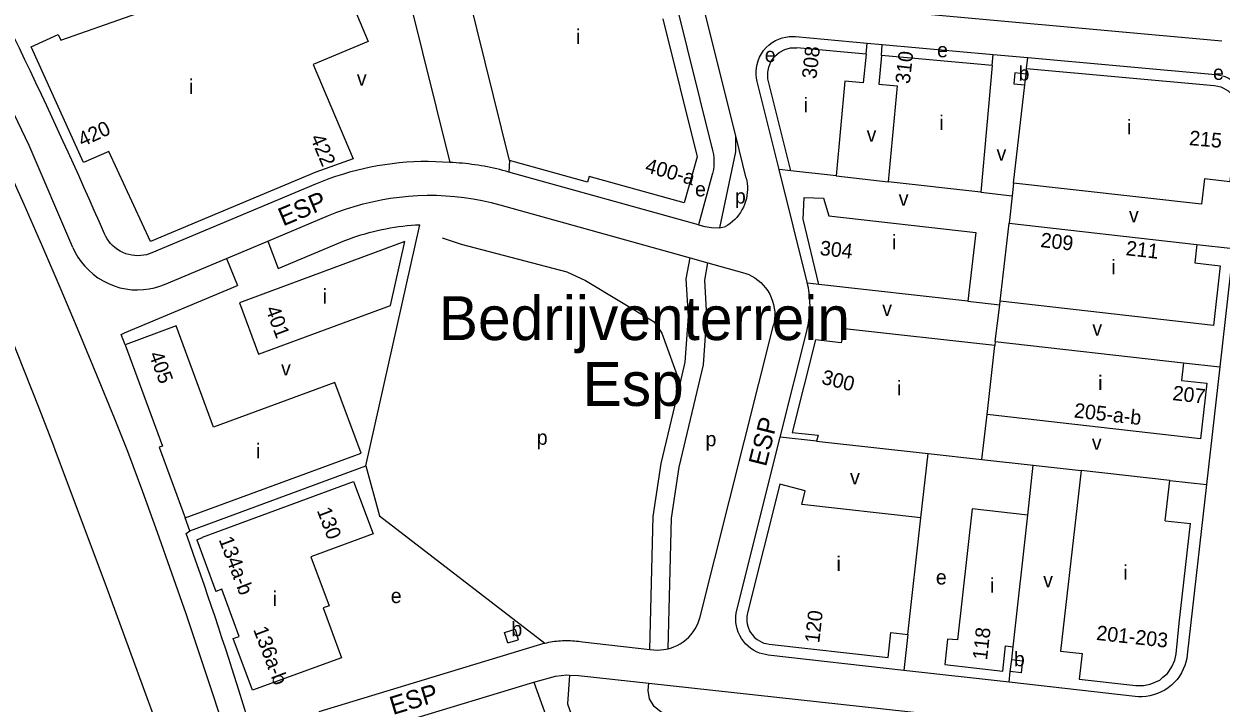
# Model space of a CAD drawing. Extents: x 161394 to 163917, y 388470 to 389774.
# Drawn here: x 162013.8 to 162341, y 388680.9 to 388866.6 of the extents above; entities that cross this region are included whole.
import ezdxf

# ---------------------------------------------------------------- set-up
doc = ezdxf.new("R2010")
doc.units = 0
for name, color, linetype in [('BLT_Basislijn', 7, 'Continuous'), ('BLT_Bebouwing', 7, 'Continuous'), ('BLT_Centroide', 7, 'Continuous'), ('BLT_Huisnummer', 7, 'Continuous'), ('BLT_Huisnummer_reeks', 7, 'Continuous'), ('BLT_Onderverdeling_panden', 7, 'Continuous'), ('BLT_Sport_parknaam', 7, 'Continuous'), ('BLT_Straatnaam', 7, 'Continuous')]:
    doc.layers.add(name, color=color, linetype=linetype)

msp = doc.modelspace()

# ---------------------------------------------------------------- linework, layer by layer
at = {"layer": 'BLT_Basislijn'}
for p, q in [((162208.3, 388835.99), (162177.66, 388959.39)), ((162184.9, 388900.77), (162201.98, 388831.99)), ((162115.96, 388886.06), (162130.14, 388828.74)), ((162224.68, 388863.18), (162244.2, 388861.4)), ((162243.91, 388858.4), (162244.2, 388861.4)), ((162244.2, 388861.4), (162248.37, 388861.03)), ((162248.1, 388858), (162248.37, 388861.03)), ((162248.37, 388861.03), (162278.68, 388858.28)), ((162278.4, 388855.26), (162278.68, 388858.28)), ((162278.68, 388858.28), (162288.15, 388857.42)), ((162287.81, 388854.44), (162288.15, 388857.42)), ((162288.15, 388857.42), (162339.39, 388852.77)), ((162220.16, 388826.82), (162214.18, 388850.93)), ((162211.16, 388824.48), (162208.3, 388835.99)), ((162146.51, 388829.3), (162146.3, 388826.13)), ((162198.08, 388811.72), (162146.3, 388826.13)), ((162201.89, 388825.42), (162198.08, 388811.72)), ((162223.34, 388826.46), (162220.16, 388826.82)), ((162227.81, 388796.04), (162220.16, 388826.82)), ((162093.4, 388822.78), (162048.7, 388804)), ((162235.71, 388825.07), (162249.94, 388823.46)), ((162284.26, 388823.09), (162283.87, 388819.63)), ((162275.28, 388820.6), (162283.87, 388819.63)), ((162283.87, 388819.63), (162283.02, 388812.13)), ((162107.21, 388745.76), (162121.96, 388811.73)), ((162203.94, 388810.88), (162205.52, 388811.2)), ((162080.43, 388807.25), (162083.22, 388799.74)), ((162083.22, 388799.74), (162100.38, 388806.95)), ((162334.33, 388806.33), (162344.29, 388805.2)), ((162069.14, 388802.5), (162072.16, 388795.09)), ((162344.29, 388805.2), (162340.62, 388772.81)), ((162231.06, 388795.4), (162227.88, 388795.76)), ((162041.25, 388782.11), (162072.16, 388795.09)), ((162271.76, 388790.8), (162280.49, 388789.81)), ((162279.22, 388779.76), (162280.49, 388789.81)), ((162280.49, 388789.81), (162280.61, 388790.77)), ((162220.48, 388753.65), (162227.8, 388782.93)), ((162330.69, 388773.97), (162340.62, 388772.81)), ((162340.62, 388772.81), (162336.99, 388740.67)), ((162208.62, 388706.26), (162220.48, 388753.65)), ((162230.39, 388752.55), (162220.48, 388753.65)), ((162258.9, 388731.55), (162260.87, 388749.17)), ((162275.6, 388747.53), (162289.56, 388745.96)), ((162059.13, 388728.01), (162107.21, 388745.76)), ((162288.1, 388732.32), (162289.56, 388745.96)), ((162289.56, 388745.96), (162302.68, 388744.48)), ((162326.94, 388741.74), (162336.99, 388740.67)), ((162336.99, 388740.67), (162331.72, 388694.05)), ((162255.34, 388699.68), (162254.28, 388689.82)), ((162254.28, 388689.82), (162217.19, 388694.02)), ((162283, 388686.57), (162254.28, 388689.82)), ((162317.45, 388682.68), (162283, 388686.57))]:
    msp.add_line(p, q, dxfattribs=at)
for points in [[(162027.15, 388805.45), (162015.14, 388833.36), (161997.8, 388869.55), (161974.18, 388914.29), (161961.92, 388936.27)], [(162035.78, 388809.19), (162034.39, 388812.39), (162032.98, 388815.59), (162031.57, 388818.79), (162030.16, 388821.98), (162028.73, 388825.16), (162027.3, 388828.35), (162025.85, 388831.53), (162024.4, 388834.7), (162022.94, 388837.88), (162021.48, 388841.05), (162020, 388844.21), (162018.52, 388847.37), (162017.03, 388850.53), (162015.53, 388853.68), (162014.02, 388856.83), (162012.51, 388859.98), (162010.98, 388863.12), (162009.45, 388866.26), (162007.91, 388869.39)], [(162341.2, 388861.95), (162241.66, 388870.97)], [(162214.18, 388850.93), (162214.01, 388851.78), (162213.91, 388852.68), (162213.89, 388853.62), (162213.97, 388854.59), (162214.15, 388855.57), (162214.43, 388856.56), (162214.82, 388857.53), (162215.33, 388858.46), (162215.93, 388859.34), (162216.63, 388860.16), (162217.41, 388860.89), (162218.26, 388861.53), (162219.16, 388862.07), (162220.09, 388862.5), (162221.03, 388862.83), (162221.98, 388863.05), (162222.91, 388863.18), (162223.81, 388863.22), (162224.68, 388863.18)], [(162339.39, 388852.77), (162340.14, 388852.68), (162340.9, 388852.53), (162341.67, 388852.31), (162342.44, 388852.03), (162343.19, 388851.67), (162343.92, 388851.24), (162344.63, 388850.75), (162345.29, 388850.19), (162345.91, 388849.57), (162346.47, 388848.9), (162346.96, 388848.18), (162347.39, 388847.43), (162347.75, 388846.65), (162348.04, 388845.85), (162348.25, 388845.04), (162348.4, 388844.24), (162348.47, 388843.44), (162348.49, 388842.67), (162348.44, 388841.91)], [(162087.86, 388607.87), (162087.24, 388610.3), (162084.83, 388619.37), (162082.34, 388628.43), (162079.77, 388637.46), (162079.66, 388637.83), (162076.25, 388649.13), (162072.76, 388660.41), (162069.19, 388671.66), (162065.55, 388682.89), (162061.84, 388694.09), (162058.05, 388705.27), (162054.18, 388716.42), (162050.23, 388727.55), (162046.22, 388738.65), (162042.12, 388749.72), (162038.47, 388758.81), (162033.68, 388770.55), (162028.82, 388782.27), (162023.88, 388793.95), (162018.87, 388805.6), (162013.78, 388817.22), (162008.62, 388828.81), (162003.19, 388840.81)], [(162203.94, 388810.88), (162208.3, 388831.66), (162208.3, 388835.99)], [(162201.98, 388831.99), (162202.06, 388831.65), (162202.13, 388831.31), (162202.19, 388830.97), (162202.24, 388830.62), (162202.29, 388830.28), (162202.32, 388829.93), (162202.34, 388829.58), (162202.36, 388829.23), (162202.36, 388828.88), (162202.36, 388828.52), (162202.34, 388828.17), (162202.32, 388827.82), (162202.29, 388827.47), (162202.24, 388827.13), (162202.19, 388826.78), (162202.13, 388826.44), (162202.06, 388826.1), (162201.98, 388825.76), (162201.89, 388825.42)], [(162130.14, 388828.74), (162128.19, 388828.87), (162126.22, 388828.96), (162124.25, 388828.99), (162122.27, 388828.98), (162120.3, 388828.91), (162118.32, 388828.79), (162116.34, 388828.63), (162114.36, 388828.41), (162112.39, 388828.14), (162110.43, 388827.82), (162108.48, 388827.45), (162106.54, 388827.04), (162104.61, 388826.57), (162102.69, 388826.05), (162100.79, 388825.49), (162098.91, 388824.88), (162097.06, 388824.23), (162095.22, 388823.53), (162093.4, 388822.78)], [(162146.3, 388826.13), (162145.47, 388826.36), (162144.64, 388826.59), (162143.8, 388826.8), (162142.96, 388827), (162142.12, 388827.19), (162141.27, 388827.37), (162140.43, 388827.54), (162139.58, 388827.7), (162138.73, 388827.85), (162137.87, 388827.99), (162137.02, 388828.12), (162136.16, 388828.23), (162135.3, 388828.34), (162134.45, 388828.43), (162133.59, 388828.52), (162132.73, 388828.59), (162131.87, 388828.65), (162131.01, 388828.7), (162130.14, 388828.74)], [(162211.16, 388824.48), (162211.32, 388823.73), (162211.44, 388822.96), (162211.5, 388822.17), (162211.51, 388821.36), (162211.47, 388820.54), (162211.37, 388819.72), (162211.21, 388818.9), (162210.99, 388818.09), (162210.72, 388817.29), (162210.39, 388816.52), (162210.01, 388815.77), (162209.57, 388815.05), (162209.1, 388814.36), (162208.57, 388813.72), (162208.02, 388813.12), (162207.43, 388812.57), (162206.81, 388812.06), (162206.18, 388811.61), (162205.52, 388811.2)], [(162097.01, 388814.21), (162099.3, 388815.13), (162101.65, 388815.97), (162104.02, 388816.74), (162106.44, 388817.42), (162108.89, 388818.02), (162111.36, 388818.53), (162113.85, 388818.96), (162116.37, 388819.3), (162118.89, 388819.55), (162121.43, 388819.71), (162123.96, 388819.78), (162126.5, 388819.76), (162129.02, 388819.65), (162131.54, 388819.45), (162134.05, 388819.16), (162136.53, 388818.79), (162138.98, 388818.33), (162141.41, 388817.79), (162143.81, 388817.17)], [(162143.81, 388817.17), (162195.87, 388802.68)], [(162080.43, 388807.25), (162097.01, 388814.21)], [(162048.7, 388804), (162048, 388803.74), (162047.27, 388803.52), (162046.5, 388803.36), (162045.7, 388803.26), (162044.89, 388803.23), (162044.05, 388803.26), (162043.22, 388803.36), (162042.39, 388803.54), (162041.57, 388803.79), (162040.78, 388804.11), (162040.01, 388804.49), (162039.29, 388804.94), (162038.62, 388805.45), (162037.99, 388806), (162037.43, 388806.59), (162036.92, 388807.21), (162036.48, 388807.86), (162036.1, 388808.52), (162035.78, 388809.19)], [(162100.38, 388806.95), (162101.46, 388807.39), (162102.55, 388807.8), (162103.65, 388808.2), (162104.75, 388808.58), (162105.87, 388808.93), (162106.99, 388809.27), (162108.12, 388809.59), (162109.25, 388809.88), (162110.39, 388810.16), (162111.54, 388810.41), (162112.68, 388810.64), (162113.84, 388810.85), (162114.99, 388811.04), (162116.15, 388811.21), (162117.31, 388811.36), (162118.47, 388811.48), (162119.64, 388811.58), (162120.8, 388811.67), (162121.96, 388811.73)], [(162198.08, 388811.72), (162199.85, 388811.26), (162201.68, 388810.97), (162203.94, 388810.88)], [(162069.14, 388802.5), (162080.43, 388807.25)], [(162128.03, 388808.11), (162133.24, 388806.41), (162162.1, 388798.84), (162167.23, 388796.44), (162186.04, 388785.13), (162188.14, 388782.09), (162193.08, 388768.2)], [(162027.15, 388805.45), (162027.77, 388804.15), (162028.51, 388802.87), (162029.37, 388801.61), (162030.35, 388800.4), (162031.45, 388799.26), (162032.66, 388798.19), (162033.97, 388797.21), (162035.37, 388796.35), (162036.85, 388795.6), (162038.39, 388794.98), (162039.97, 388794.5), (162041.58, 388794.15), (162043.2, 388793.95), (162044.81, 388793.89), (162046.4, 388793.96), (162047.94, 388794.15), (162049.43, 388794.46), (162050.85, 388794.88), (162052.2, 388795.39)], [(162052.2, 388795.39), (162069.14, 388802.5)], [(162193.08, 388768.2), (162194.49, 388774.16), (162195.41, 388786.62), (162194.78, 388796.92), (162195.87, 388802.68)], [(162195.87, 388802.68), (162200.71, 388801.33)], [(162189.79, 388695.72), (162190.74, 388731.5), (162192.85, 388745.42), (162199.45, 388773.4), (162200.42, 388786.59), (162199.81, 388796.6), (162200.71, 388801.33)], [(162200.71, 388801.33), (162210.19, 388798.69)], [(162210.19, 388798.69), (162211.04, 388798.42), (162211.89, 388798.07), (162212.74, 388797.65), (162213.56, 388797.16), (162214.36, 388796.59), (162215.12, 388795.94), (162215.83, 388795.22), (162216.48, 388794.44), (162217.07, 388793.6), (162217.59, 388792.72), (162218.03, 388791.79), (162218.38, 388790.84), (162218.65, 388789.86), (162218.84, 388788.88), (162218.95, 388787.91), (162218.97, 388786.95), (162218.92, 388786), (162218.8, 388785.09), (162218.61, 388784.22)], [(162227.8, 388782.93), (162227.95, 388783.59), (162228.09, 388784.25), (162228.22, 388784.92), (162228.32, 388785.59), (162228.41, 388786.27), (162228.49, 388786.95), (162228.54, 388787.63), (162228.58, 388788.31), (162228.6, 388789), (162228.61, 388789.68), (162228.59, 388790.37), (162228.56, 388791.05), (162228.52, 388791.73), (162228.45, 388792.41), (162228.37, 388793.09), (162228.27, 388793.76), (162228.15, 388794.43), (162228.02, 388795.1), (162227.88, 388795.76)], [(162227.88, 388795.76), (162227.87, 388795.77), (162227.87, 388795.79), (162227.87, 388795.8), (162227.86, 388795.82), (162227.86, 388795.83), (162227.85, 388795.85), (162227.85, 388795.86), (162227.85, 388795.88), (162227.84, 388795.89), (162227.84, 388795.91), (162227.84, 388795.92), (162227.83, 388795.93), (162227.83, 388795.95), (162227.83, 388795.96), (162227.82, 388795.98), (162227.82, 388795.99), (162227.82, 388796.01), (162227.81, 388796.02), (162227.81, 388796.04)], [(162198.57, 388704.48), (162218.61, 388784.22)], [(162099.69, 388494.38), (162091.65, 388531.25), (162090.66, 388536.53), (162089.19, 388544.02), (162087.64, 388551.5), (162086, 388558.97), (162084.3, 388566.41), (162082.51, 388573.84), (162080.64, 388581.25), (162078.7, 388588.64), (162076.68, 388596.01), (162074.59, 388603.36), (162072.41, 388610.68), (162070.16, 388617.98), (162067.84, 388625.26), (162065.43, 388632.51), (162062.96, 388639.74), (162060.4, 388646.94), (162036.19, 388712.95), (162022.35, 388749.92), (162021.79, 388751.4), (162017.9, 388761.55), (162013.94, 388771.67), (162009.9, 388781.76)], [(162041.38, 388778.89), (162040.34, 388781.73), (162041.25, 388782.11)], [(162184.79, 388695.57), (162185.75, 388731.95), (162187.94, 388746.37), (162193.08, 388768.2)], [(162107.21, 388745.76), (162110.92, 388732.1), (162156.12, 388697.27)], [(162059.13, 388728.01), (162057.83, 388731.53)], [(162076.06, 388672.96), (162072.49, 388684.45), (162070.66, 388690.18), (162069.74, 388693.05), (162068.81, 388695.91), (162067.87, 388698.77), (162066.93, 388701.62), (162065.98, 388704.48), (162065.02, 388707.33), (162064.05, 388710.18), (162063.08, 388713.03), (162062.1, 388715.87), (162061.12, 388718.72), (162060.13, 388721.56), (162059.13, 388724.4), (162058.12, 388727.23), (162059.13, 388728.01)], [(162189.79, 388695.72), (162190.73, 388696.01), (162191.41, 388696.26), (162192.3, 388696.65), (162193.15, 388697.13), (162193.97, 388697.67), (162194.74, 388698.27), (162195.45, 388698.93), (162196.1, 388699.65), (162196.69, 388700.4), (162197.21, 388701.18), (162197.65, 388701.99), (162198.03, 388702.82), (162198.34, 388703.65), (162198.57, 388704.48)], [(162217.19, 388694.02), (162216.4, 388694.13), (162215.59, 388694.32), (162214.78, 388694.58), (162213.97, 388694.92), (162213.18, 388695.35), (162212.41, 388695.85), (162211.69, 388696.43), (162211.01, 388697.08), (162210.4, 388697.8), (162209.85, 388698.58), (162209.39, 388699.41), (162209, 388700.27), (162208.71, 388701.15), (162208.5, 388702.04), (162208.37, 388702.93), (162208.33, 388703.8), (162208.36, 388704.66), (162208.46, 388705.48), (162208.62, 388706.26)], [(162156.12, 388697.27), (162156.65, 388697.4), (162157.18, 388697.51), (162157.71, 388697.61), (162158.25, 388697.7), (162158.79, 388697.78), (162159.33, 388697.84), (162159.88, 388697.9), (162160.42, 388697.94), (162160.97, 388697.97), (162161.52, 388697.99), (162162.06, 388698), (162162.61, 388698), (162163.16, 388697.98), (162163.7, 388697.95), (162164.25, 388697.91), (162164.79, 388697.86), (162165.33, 388697.8), (162165.87, 388697.73), (162166.41, 388697.64)], [(162166.41, 388697.64), (162184.79, 388695.57)], [(162156.12, 388697.27), (162094.32, 388678.5)], [(162184.79, 388695.57), (162185.95, 388695.43), (162186.83, 388695.39), (162187.73, 388695.42), (162188.65, 388695.51), (162189.79, 388695.72)], [(162283.73, 388692.77), (162284.11, 388696.28)], [(162331.72, 388694.05), (162331.57, 388693.09), (162331.35, 388692.11), (162331.04, 388691.13), (162330.64, 388690.15), (162330.15, 388689.2), (162329.58, 388688.27), (162328.92, 388687.38), (162328.18, 388686.54), (162327.37, 388685.77), (162326.49, 388685.07), (162325.56, 388684.45), (162324.58, 388683.92), (162323.56, 388683.47), (162322.53, 388683.12), (162321.49, 388682.86), (162320.45, 388682.69), (162319.42, 388682.61), (162318.42, 388682.61), (162317.45, 388682.68)], [(162153.13, 388686.65), (162159.08, 388688.24), (162162.14, 388688.58), (162162.85, 388688.54)], [(162162.85, 388688.54), (162162.3, 388680.7), (162171.01, 388656.24), (162175.86, 388657.98)], [(162162.85, 388688.54), (162165.36, 388688.4), (162184.54, 388686.31)], [(162283, 388686.57), (162283.34, 388689.5)], [(162118.23, 388676.05), (162153.13, 388686.65)], [(162153.13, 388686.65), (162156.39, 388677.5)], [(162190.14, 388677.75), (162187.93, 388678.41), (162185.98, 388679.93), (162184.73, 388682.07), (162184.37, 388684.35), (162184.54, 388686.31)], [(162184.54, 388686.31), (162313.68, 388672.24)]]:
    msp.add_lwpolyline(points, dxfattribs=at)
at = {"layer": 'BLT_Bebouwing'}
for p, q in [((162146.51, 388829.3), (162132.02, 388887.65)), ((162188.42, 388867.99), (162197.76, 388830.33)), ((162243.91, 388858.4), (162225.01, 388860.1)), ((162167.8, 388823.37), (162146.51, 388829.3)), ((162197.76, 388830.33), (162194.24, 388817.67)), ((162168.23, 388824.91), (162167.8, 388823.37)), ((162194.24, 388817.67), (162168.23, 388824.91)), ((162238.05, 388783.23), (162237.09, 388779.45)), ((162279.09, 388778.66), (162238.05, 388783.23)), ((162230.06, 388780.24), (162223.72, 388754.89)), ((162237.09, 388779.45), (162230.06, 388780.24)), ((162279.22, 388779.76), (162279.09, 388778.66)), ((162279.22, 388779.76), (162330.69, 388773.97)), ((162330.69, 388773.97), (162330.12, 388769.13)), ((162330.12, 388769.13), (162337.09, 388768.35)), ((162337.09, 388768.35), (162335.37, 388753.18)), ((162275.6, 388747.53), (162276.98, 388759.79)), ((162335.37, 388753.18), (162276.98, 388759.79)), ((162230.79, 388754.12), (162230.39, 388752.55)), ((162230.39, 388752.55), (162260.87, 388749.17)), ((162260.87, 388749.17), (162275.6, 388747.53)), ((162302.68, 388744.48), (162297.05, 388695.11)), ((162326.94, 388741.74), (162302.68, 388744.48)), ((162220.31, 388740.72), (162211.53, 388705.53)), ((162227.25, 388738.96), (162220.31, 388740.72)), ((162325.67, 388730.76), (162326.94, 388741.74)), ((162226.35, 388735.22), (162227.25, 388738.96)), ((162258.9, 388731.55), (162226.35, 388735.22)), ((162255.34, 388699.68), (162258.9, 388731.55)), ((162284.11, 388696.28), (162288.1, 388732.32)), ((162325.67, 388730.76), (162332.56, 388729.97)), ((162060.98, 388725.58), (162066.21, 388711.42)), ((162145.11, 388700.2), (162147.98, 388701.07)), ((162147.98, 388701.07), (162148.86, 388698.2)), ((162145.99, 388697.33), (162145.11, 388700.2)), ((162145.99, 388697.33), (162148.86, 388698.2)), ((162249.92, 388693.32), (162250.68, 388700.18)), ((162250.68, 388700.18), (162255.34, 388699.68)), ((162217.45, 388697.01), (162249.92, 388693.32)), ((162297.05, 388695.11), (162302.96, 388694.44)), ((162302.96, 388694.44), (162302.15, 388687.47)), ((162265.45, 388691.4), (162281.31, 388689.64)), ((162283.34, 388689.5), (162283.73, 388692.77)), ((162302.15, 388687.47), (162317.66, 388685.68))]:
    msp.add_line(p, q, dxfattribs=at)
for points in [[(162015.75, 388860.39), (162023.09, 388863.77), (162023.86, 388862.24), (162081.55, 388882.48), (162096.9, 388887.92), (162107.86, 388861.83), (162092.8, 388855.5), (162103.73, 388829.7), (162093.51, 388826.06), (162069.87, 388816.15), (162048.35, 388807.09), (162048.34, 388807.1), (162048.35, 388807.09), (162036.94, 388831.79), (162030.04, 388828.74)], [(162072.67, 388790.4), (162077.87, 388776.3), (162113.98, 388789.65), (162117.87, 388807.13)]]:
    msp.add_lwpolyline(points, close=True, dxfattribs=at)
for points in [[(162223.34, 388826.46), (162217.09, 388851.65), (162217.06, 388853.47), (162217.31, 388854.85), (162217.91, 388856.31), (162218.92, 388857.72), (162220.17, 388858.81), (162221.68, 388859.63), (162223.31, 388860.07), (162225.01, 388860.1)], [(162243.91, 388858.4), (162243.16, 388850.52), (162238.15, 388850.99), (162235.71, 388825.07)], [(162248.1, 388858), (162247.39, 388850.14), (162252.4, 388849.66), (162249.94, 388823.46)], [(162278.4, 388855.26), (162248.1, 388858)], [(162278.4, 388855.26), (162275.28, 388820.6)], [(162287.64, 388852.94), (162284.62, 388853.24), (162284.33, 388850.26), (162287.3, 388849.97)], [(162287.64, 388852.94), (162287.81, 388854.44)], [(162287.81, 388854.44), (162339.11, 388849.78), (162340.07, 388849.63), (162340.9, 388849.4), (162341.64, 388849.08), (162342.29, 388848.73), (162342.9, 388848.3), (162343.45, 388847.82), (162343.94, 388847.26), (162344.43, 388846.63), (162344.79, 388845.97), (162345.05, 388845.4), (162345.24, 388844.73), (162345.43, 388843.96), (162345.5, 388843.35), (162345.5, 388842.68), (162345.44, 388841.77), (162343.36, 388823.49)], [(162284.26, 388823.09), (162287.3, 388849.97)], [(162235.71, 388825.07), (162223.34, 388826.46)], [(162275.28, 388820.6), (162249.94, 388823.46)], [(162343.36, 388823.49), (162336.4, 388824.26), (162335.6, 388817.32), (162284.26, 388823.09)], [(162231.06, 388795.4), (162226.73, 388813.28), (162227, 388819.14), (162232.27, 388818.94), (162233.76, 388814.13), (162273.89, 388809.61), (162271.76, 388790.8)], [(162280.61, 388790.77), (162283.02, 388812.13)], [(162283.02, 388812.13), (162334.33, 388806.33)], [(162334.33, 388806.33), (162333.76, 388801.27), (162340.72, 388800.49), (162338.87, 388784.18), (162280.61, 388790.77)], [(162271.76, 388790.8), (162231.06, 388795.4)], [(162105.91, 388749.28), (162098.75, 388768.58), (162065.55, 388756.32), (162055.36, 388784.05), (162041.38, 388778.89)], [(162041.38, 388778.89), (162051.61, 388751.18), (162050.72, 388750.85), (162057.83, 388731.53)], [(162223.72, 388754.89), (162230.79, 388754.12)], [(162057.83, 388731.53), (162105.91, 388749.28)], [(162060.98, 388725.58), (162062.6, 388726.17), (162062.57, 388726.27), (162103.86, 388741.53), (162109.16, 388727.21), (162092.2, 388720.9), (162097.19, 388707.51), (162095.53, 388706.94), (162100.56, 388693.3), (162076.21, 388684.4), (162070.95, 388698.55), (162072.57, 388699.14), (162067.82, 388712.03), (162066.21, 388711.42)], [(162288.1, 388732.32), (162272.94, 388734.02), (162268.94, 388698.17)], [(162317.66, 388685.68), (162319.77, 388685.7), (162321.62, 388686.05), (162324.23, 388687.18), (162325.07, 388688.02), (162326.29, 388689), (162327.54, 388690.79), (162328.32, 388692.59), (162328.67, 388694.38), (162329.52, 388702.72), (162332.56, 388729.97)], [(162211.53, 388705.53), (162211.42, 388705.04), (162211.36, 388704.54), (162211.34, 388703.94), (162211.34, 388703.2), (162211.46, 388702.55), (162211.59, 388701.93), (162211.8, 388701.36), (162212.08, 388700.69), (162212.37, 388700.16), (162212.77, 388699.61), (162213.43, 388698.87), (162214.13, 388698.32), (162214.78, 388697.9), (162215.42, 388697.54), (162215.97, 388697.32)], [(162268.94, 388698.17), (162266.2, 388698.41), (162265.45, 388691.4)], [(162215.97, 388697.32), (162216.6, 388697.16), (162217.45, 388697.01)], [(162281.31, 388689.64), (162282.07, 388696.5), (162284.11, 388696.28)], [(162283.73, 388692.77), (162286.71, 388692.42), (162286.32, 388689.14), (162283.34, 388689.5)]]:
    msp.add_lwpolyline(points, dxfattribs=at)
at = {"layer": 'BLT_Onderverdeling_panden'}
for p, q in [((162287.3, 388849.97), (162287.64, 388852.94)), ((162276.98, 388759.79), (162279.09, 388778.66))]:
    msp.add_line(p, q, dxfattribs=at)

# ---------------------------------------------------------------- texts
at = {"layer": 'BLT_Centroide'}
for s, p in [('i', (162164.61, 388861.19)), ('e', (162216.24, 388856.21)), ('e', (162263.34, 388857.51)), ('b', (162285.6, 388851.14)), ('i', (162058.88, 388847.5)), ('v', (162104.75, 388849.77)), ('e', (162338.75, 388851.34)), ('i', (162226.9, 388842.47)), ('i', (162263.95, 388837.63)), ('i', (162315.28, 388836.44)), ('v', (162244.08, 388834.48)), ('v', (162279.59, 388829.27)), ('e', (162197.18, 388819.46)), ('p', (162208.08, 388817.51)), ('v', (162252.85, 388816.93)), ('v', (162315.78, 388812.4)), ('i', (162251.05, 388804.97)), ('i', (162310.95, 388798.16)), ('i', (162095.38, 388790.17)), ('v', (162248.33, 388786.77)), ('v', (162305.77, 388781.42)), ('v', (162084.02, 388770.49)), ('i', (162307.37, 388766.47)), ('i', (162252.35, 388765.03)), ('p', (162153.92, 388751.54)), ('p', (162200.04, 388751.13)), ('v', (162305.64, 388750.16)), ('i', (162077.15, 388747.86)), ('v', (162239.55, 388740.7)), ('i', (162235.84, 388717.03)), ('i', (162314.22, 388714.62)), ('e', (162263, 388713.33)), ('i', (162277.77, 388711.08)), ('v', (162292.34, 388712.59)), ('i', (162081.74, 388707.47)), ('e', (162114.01, 388708.24)), ('b', (162146.98, 388699.16)), ('b', (162284.33, 388690.95))]:
    msp.add_text(s, height=4, dxfattribs=at).set_placement(p)
at = {"layer": 'BLT_Huisnummer'}
for s, rotation, p in [('308', 83.5474, (162230.33, 388851.45)), ('310', 83.5502, (162255.85, 388850.1)), ('215', 354.8173, (162332.12, 388833.52)), ('304', 353.5497, (162231.15, 388803.45)), ('401', 290.3772, (162079.71, 388788.69)), ('405', 290.2627, (162047.84, 388776.25)), ('300', 345.9568, (162231.52, 388768.27)), ('120', 83.5488, (162231.12, 388697.15)), ('118', 83.5488, (162276.98, 388692.52))]:
    msp.add_text(s, height=4, rotation=rotation, dxfattribs=at).set_placement(p)
at = {"layer": 'BLT_Huisnummer_reeks'}
for s, rotation, p in [('420', 24.8417, (162029.69, 388832.92)), ('422', 292.7898, (162091.93, 388835.53)), ('400-a', 344.4456, (162183.31, 388826.14)), ('209', 353.5499, (162291.46, 388805.63)), ('211', 353.5499, (162314.79, 388803.4)), ('207', 353.3736, (162327.54, 388763.78)), ('205-a-b', 353.3736, (162300.61, 388759.03)), ('130', 290.7643, (162093.75, 388733.61)), ('134a-b', 290.7643, (162066.94, 388725.62)), ('136a-b', 290.7643, (162076.36, 388701.03)), ('201-203', 353.6776, (162306.71, 388698.18))]:
    msp.add_text(s, height=4, rotation=rotation, dxfattribs=at).set_placement(p)
at = {"layer": 'BLT_Sport_parknaam'}
for s, p in [('Bedrijventerrein', (162127.15, 388780.17)), ('Esp', (162166.44, 388762.17))]:
    msp.add_text(s, height=12, dxfattribs=at).set_placement(p)
at = {"layer": 'BLT_Straatnaam'}
for rotation, p in [(22.7882, (162084.59, 388811.24)), (75.9597, (162216.57, 388745.37)), (16.8942, (162114.62, 388677.61))]:
    msp.add_text('ESP', height=5, rotation=rotation, dxfattribs=at).set_placement(p)

doc.saveas('drawing.dxf')
